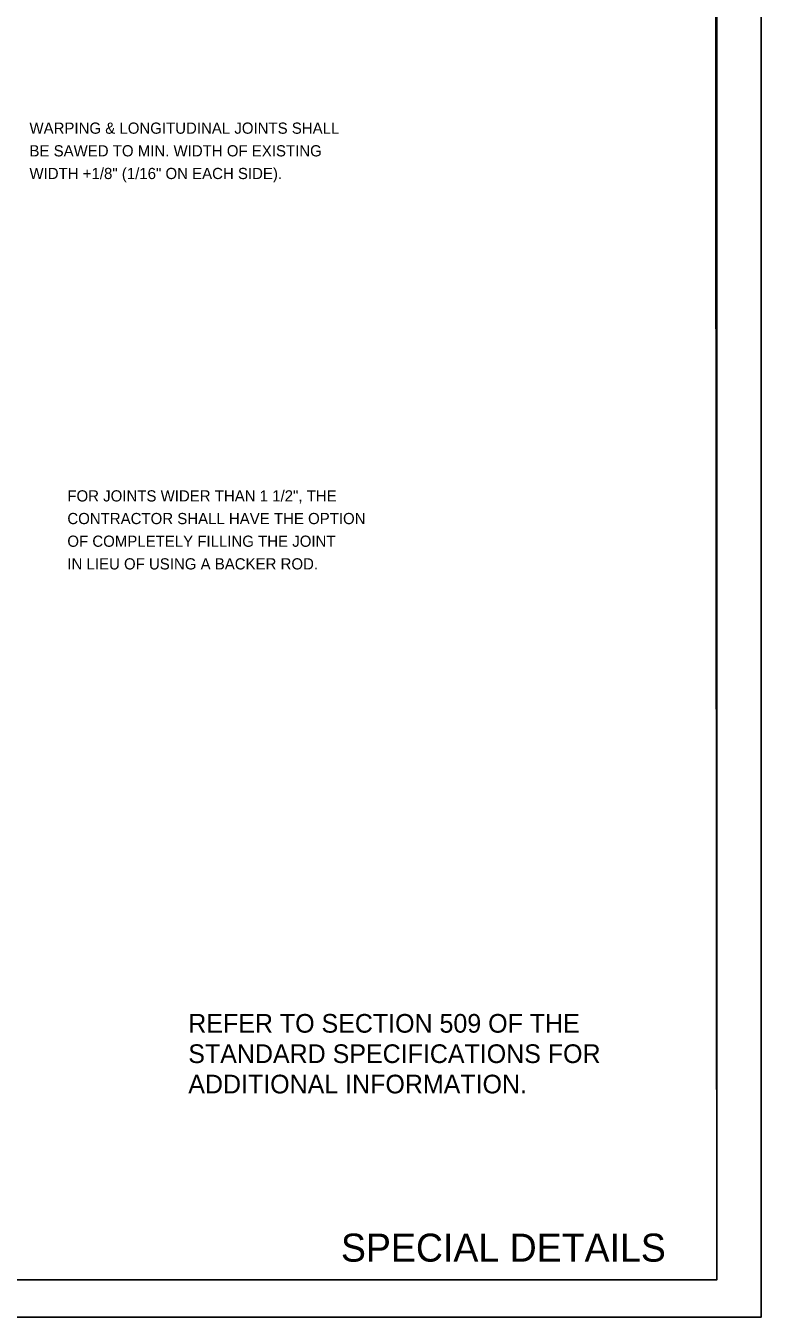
# Model space of a CAD drawing. Extents: x 1375738 to 1375905, y 380661 to 380875.
# Drawn here: x 1375865.5 to 1375904.9, y 380661.4 to 380730.5 of the extents above; entities that cross this region are included whole.
import ezdxf

# ---------------------------------------------------------------- set-up
doc = ezdxf.new("R2010")
doc.units = 0
for name, color, linetype in [('R_Border', 7, 'Continuous'), ('R_Draft', 7, 'Continuous'), ('R_No Plot', 7, 'Continuous')]:
    doc.layers.add(name, color=color, linetype=linetype)

msp = doc.modelspace()

# ---------------------------------------------------------------- linework, layer by layer
at = {"layer": 'R_Border'}
for q in [(1375902.509, 380766.114), (1375744.419, 380663.384)]:
    msp.add_line((1375902.509, 380663.384), q, dxfattribs=at)
at = {"layer": 'R_No Plot'}
msp.add_line((1375738.219, 380661.395), (1375904.885, 380661.395), dxfattribs=at)
for points in [[(1375738.215, 380768.061), (1375904.885, 380768.061), (1375904.885, 380661.392), (1375738.215, 380661.392)], [(1375861.379, 380766.114), (1375871.189, 380766.114), (1375871.189, 380761.174), (1375879.245, 380761.174), (1375890.845, 380761.174), (1375890.845, 380744.839), (1375902.449, 380744.839), (1375902.509, 380663.384), (1375744.419, 380663.384), (1375744.419, 380766.114)]]:
    msp.add_lwpolyline(points, close=True, dxfattribs=at)

# ---------------------------------------------------------------- texts
at = {"layer": 'R_Border'}
msp.add_text('SPECIAL DETAILS', height=1.5, dxfattribs=at).set_placement((1375882.391, 380664.364))
at = {"layer": 'R_Draft'}
for s, height, p in [('WARPING & LONGITUDINAL JOINTS SHALL', 0.6, (1375865.719, 380724.739)), ('BE SAWED TO MIN. WIDTH OF EXISTING', 0.6, (1375865.719, 380723.526)), ('WIDTH +1/8" (1/16" ON EACH SIDE).', 0.6, (1375865.719, 380722.313)), ('FOR JOINTS WIDER THAN 1 1/2", THE', 0.6, (1375867.747, 380705.055)), ('CONTRACTOR SHALL HAVE THE OPTION', 0.6, (1375867.747, 380703.842)), ('OF COMPLETELY FILLING THE JOINT', 0.6, (1375867.747, 380702.629)), ('IN LIEU OF USING A BACKER ROD. ', 0.6, (1375867.747, 380701.416)), ('REFER TO SECTION 509 OF THE', 1, (1375874.221, 380676.621)), ('STANDARD SPECIFICATIONS FOR', 1, (1375874.221, 380674.996)), ('ADDITIONAL INFORMATION.', 1, (1375874.221, 380673.371))]:
    msp.add_text(s, height=height, dxfattribs=at).set_placement(p)

doc.saveas('drawing.dxf')
